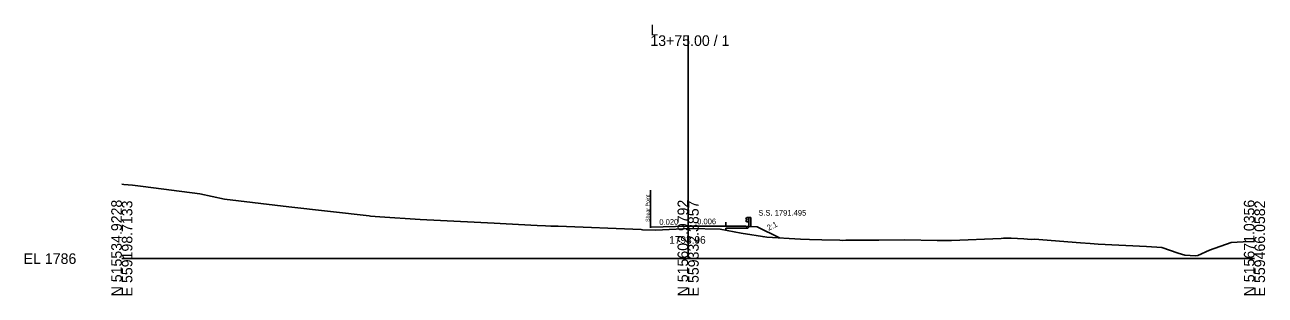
# Model space of a CAD drawing. Extents: x -26 to 1303, y -10 to 9545.
# Drawn here: x 974.3 to 1302.8, y 490.3 to 562 of the extents above; entities that cross this region are included whole.
import ezdxf

# ---------------------------------------------------------------- set-up
doc = ezdxf.new("R2010")
doc.units = 0
for name, color, linetype in [('Exist Cross Section Cell', 7, 'Continuous'), ('Exist XS Center Line Elevation Label', 7, 'Continuous'), ('Exist XS Ground Line', 7, 'Continuous'), ('Prop XS Dump Level', 7, 'Continuous'), ('Prop XS EOT Tick Mark', 7, 'Continuous'), ('Prop XS Finish Grade', 7, 'Continuous'), ('Prop XS Finish Grade Earthwork', 7, 'Continuous'), ('Prop XS Finish Grade Paved Shoulder', 7, 'Continuous'), ('Prop XS Finish Grade Pavement', 7, 'Continuous'), ('Prop XS Guardrail', 7, 'Continuous'), ('Prop XS Pvmt Edge Slope', 7, 'Continuous'), ('Prop XS SE Text', 7, 'Continuous'), ('Prop XS Shear Point Label', 7, 'Continuous'), ('Prop XS Side Slope Text', 7, 'Continuous'), ('Prop XS SS Elevation Text', 7, 'Continuous'), ('Prop XS Subgrade Earthwork', 7, 'Continuous')]:
    doc.layers.add(name, color=color, linetype=linetype)

msp = doc.modelspace()

# ---------------------------------------------------------------- linework, layer by layer
at = {"layer": 'Exist Cross Section Cell'}
for p, q in [((1150, 500), (1150, 559.17)), ((1000, 500), (1150, 500)), ((1150, 500), (1300, 500))]:
    msp.add_line(p, q, dxfattribs=at)
at = {"layer": 'Exist XS Ground Line'}
for p, q in [((1000, 519.72), (1000.5, 519.66)), ((1000.5, 519.66), (1002.85, 519.43)), ((1002.85, 519.43), (1005.7, 519.13)), ((1005.7, 519.13), (1020.7, 517.19)), ((1020.7, 517.19), (1027.19, 515.78)), ((1027.19, 515.78), (1044.26, 513.7)), ((1044.26, 513.7), (1065.5, 511.32)), ((1065.5, 511.32), (1065.91, 511.24)), ((1065.91, 511.24), (1068.34, 511.05)), ((1068.34, 511.05), (1078.99, 510.4)), ((1078.99, 510.4), (1084.43, 510.12)), ((1084.43, 510.12), (1096.87, 509.47)), ((1096.87, 509.47), (1098.61, 509.38)), ((1098.61, 509.38), (1101.77, 509.22)), ((1101.77, 509.22), (1109.97, 508.79)), ((1109.97, 508.79), (1112.23, 508.68)), ((1112.23, 508.68), (1113.66, 508.62)), ((1113.66, 508.62), (1114.51, 508.59)), ((1114.51, 508.59), (1115.57, 508.56)), ((1115.57, 508.56), (1137.53, 507.68)), ((1137.53, 507.68), (1137.95, 507.67)), ((1137.95, 507.67), (1141.34, 507.54)), ((1141.34, 507.54), (1150.45, 507.98)), ((1150.45, 507.98), (1158.5, 507.84)), ((1158.5, 507.84), (1164.05, 506.79)), ((1164.05, 506.79), (1170.88, 505.69)), ((1170.88, 505.69), (1179.77, 505.17)), ((1179.77, 505.17), (1182.15, 505.05)), ((1182.15, 505.05), (1185.39, 504.95)), ((1185.39, 504.95), (1190.22, 504.85)), ((1190.22, 504.85), (1190.79, 504.84)), ((1190.79, 504.84), (1191.75, 504.85)), ((1191.75, 504.85), (1199.48, 504.88)), ((1199.48, 504.88), (1200.5, 504.92)), ((1200.5, 504.92), (1207.38, 504.96)), ((1207.38, 504.96), (1215.97, 504.77)), ((1215.97, 504.77), (1218.01, 504.76)), ((1218.01, 504.76), (1219.76, 504.8)), ((1219.76, 504.8), (1232.94, 505.36)), ((1232.94, 505.36), (1233.57, 505.4)), ((1233.57, 505.4), (1234.75, 505.44)), ((1234.75, 505.44), (1235.54, 505.38)), ((1235.54, 505.38), (1238.95, 505.22)), ((1238.95, 505.22), (1240.86, 505.04)), ((1240.86, 505.04), (1241.76, 505.12)), ((1241.76, 505.12), (1253.91, 504.16)), ((1253.91, 504.16), (1256.49, 504.02)), ((1256.49, 504.02), (1258.56, 503.85)), ((1258.56, 503.85), (1271.4, 503.22)), ((1271.4, 503.22), (1275.43, 502.93)), ((1275.43, 502.93), (1279.79, 501.45)), ((1288.12, 502.25), (1293.86, 504.23)), ((1293.86, 504.23), (1296.98, 504.43)), ((1296.98, 504.43), (1300, 504.57)), ((1279.79, 501.45), (1281.59, 500.92)), ((1281.59, 500.92), (1283, 500.81)), ((1283, 500.81), (1284.49, 500.74)), ((1284.49, 500.74), (1285.01, 500.84)), ((1285.01, 500.84), (1288.12, 502.25))]:
    msp.add_line(p, q, dxfattribs=at)
at = {"layer": 'Prop XS Dump Level'}
for p, q in [((1140, 508.38), (1150, 508.58)), ((1150, 508.58), (1160, 508.64))]:
    msp.add_line(p, q, dxfattribs=at)
at = {"layer": 'Prop XS EOT Tick Mark'}
msp.add_line((1160, 508.64), (1160, 509.64), dxfattribs=at)
at = {"layer": 'Prop XS Finish Grade'}
msp.add_line((1165.27, 508.61), (1166.29, 508.55), dxfattribs=at)
at = {"layer": 'Prop XS Finish Grade Earthwork'}
for p, q in [((1166.29, 508.55), (1168.27, 508.46)), ((1168.27, 508.46), (1174.21, 505.49))]:
    msp.add_line(p, q, dxfattribs=at)
at = {"layer": 'Prop XS Finish Grade Paved Shoulder'}
msp.add_line((1160, 508.64), (1165.27, 508.61), dxfattribs=at)
at = {"layer": 'Prop XS Finish Grade Pavement'}
for p, q in [((1140, 508.38), (1150, 508.58)), ((1150, 508.58), (1160, 508.64))]:
    msp.add_line(p, q, dxfattribs=at)
at = {"layer": 'Prop XS Guardrail'}
for p, q in [((1165.3, 510.66), (1165.27, 510.6)), ((1165.27, 510.6), (1165.3, 510.54)), ((1165.3, 510.05), (1165.27, 509.99)), ((1165.27, 509.99), (1165.3, 509.93)), ((1165.59, 510.86), (1165.3, 510.66)), ((1165.3, 510.54), (1165.59, 510.34)), ((1165.59, 510.25), (1165.3, 510.05)), ((1165.3, 509.93), (1165.59, 509.73)), ((1166.09, 510.86), (1165.59, 510.86)), ((1165.59, 510.34), (1165.59, 510.25)), ((1165.59, 509.73), (1166.09, 509.73)), ((1166.59, 510.86), (1166.09, 510.86)), ((1166.09, 510.86), (1166.09, 508.36)), ((1166.59, 508.36), (1166.59, 510.86))]:
    msp.add_line(p, q, dxfattribs=at)
at = {"layer": 'Prop XS Pvmt Edge Slope'}
msp.add_line((1165.27, 508.61), (1165.81, 508.07), dxfattribs=at)
at = {"layer": 'Prop XS Shear Point Label'}
msp.add_line((1140, 518.12), (1140, 508.18), dxfattribs=at)
at = {"layer": 'Prop XS Subgrade Earthwork'}
for p, q in [((1160, 508.1), (1160, 507.56)), ((1160, 508.1), (1165.81, 508.07)), ((1165.81, 508.07), (1166.29, 508.55))]:
    msp.add_line(p, q, dxfattribs=at)

# ---------------------------------------------------------------- texts
at = {"layer": 'Exist Cross Section Cell'}
for s, p in [('L', (1140, 559.17)), ('13+75.00 / 1', (1140, 556.37)), ('EL 1786', (974, 498.6))]:
    msp.add_text(s, height=2.8, dxfattribs=at).set_placement(p)
for s, p in [('N 515534.9228', (1000, 490)), ('E 559198.7133', (1002.8, 490)), ('N 515602.9792', (1150, 490)), ('E 559332.3857', (1152.8, 490)), ('N 515671.0356', (1300, 490)), ('E 559466.0582', (1302.8, 490))]:
    msp.add_text(s, height=2.8, rotation=90, dxfattribs=at).set_placement(p)
at = {"layer": 'Exist XS Center Line Elevation Label'}
msp.add_text('1793.96', height=2, dxfattribs=at).set_placement((1144.98, 503.96))
at = {"layer": 'Prop XS Dump Level'}
for s, height, p in [('Case1', 0.04, (1163, 508.46)), ('Case1', 0.04, (1163, 508.44)), ('Eop', 0.3, (1170, 505.53))]:
    msp.add_text(s, height=height, dxfattribs=at).set_placement(p)
at = {"layer": 'Prop XS SE Text'}
for s, rotation, p in [('0.020', 1.1458, (1142.38, 508.93)), ('0.006', 0.3361, (1152.39, 509.09))]:
    msp.add_text(s, height=1.5, rotation=rotation, dxfattribs=at).set_placement(p)
at = {"layer": 'Prop XS Shear Point Label'}
msp.add_text('Shear Point', height=1, rotation=90, dxfattribs=at).set_placement((1139.78, 509.74))
at = {"layer": 'Prop XS Side Slope Text'}
msp.add_text('2:1', height=1.5, rotation=26.5651, dxfattribs=at).set_placement((1171.33, 507.38))
at = {"layer": 'Prop XS SS Elevation Text'}
msp.add_text('S.S. 1791.495', height=1.5, dxfattribs=at).set_placement((1168.57, 511.39))

doc.saveas('drawing.dxf')
